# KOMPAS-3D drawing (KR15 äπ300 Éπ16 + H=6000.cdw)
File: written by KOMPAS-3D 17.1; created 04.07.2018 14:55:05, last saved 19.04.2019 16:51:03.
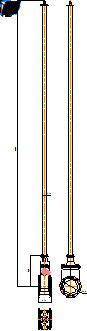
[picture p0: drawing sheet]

Sheet 1: A4, portrait

Title block, sheet 1: name: KR15 Ду300 Ру16 + / H=6000; material: Внимание! Данный продукт является объектом авторского права ООО «Торговый Дом АДЛ». / Запрещается изменение, копирование, распространение / (в том числе путем копирования на другие сайты и ресурсы в Интернете) / или любое иное использование информации и объектов без предварительного / согласия правообладателя (ООО «Торговый Дом АДЛ»).; mass: 36,7; sheets: 1; organisation: ООО "Торговый дом АДЛ"; sheet format: A4; stored path: \\adlc.lan\data\АДЛ_ПКД\3D-модели\ADL production\Клиновые задвижки серии KR ГРАНАР\Клиновые задвижки KR15 со стационарным удлинением\KOMPAS 2D\KR15 Ду300 Ру16 + H=6000.cdw

Views: Проекционный вид 6, Спереди 13, Проекционный вид 15
Referenced files in C:\Users\kka\KOMPAS_Work\Удлинения БИВАЛ ф. ADL\!Задвижки\У_ду_125-400\: Ушду125-400.a3d
Referenced files in C:\Users\kka\KOMPAS_Work\!Trash\ГРАНАР KR Задвижки с приводами и удлинениями\С приводами\: KR15 Ду300 Ру16.m3d
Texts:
  kka
  adl
  УШКЗ.100000.00.00
  Удлинение клиновой задвижки с редуктором
  Крепежное изделие ГОСТ
  Болт
  ГОСТ
  Гайка
  Лит-Масса-Масштаб
  Материал-Предприятие
  Title Specification
  Body Specification ( left align )
  Body Specificaton ( centered )
  Поз.
  Кол.
  Приме-
  чание
  Таблица спецификации
Dimensions and other numbers on the sheet: 76; 645; 270; 6000; 410; 4; 1; 58; 40Х; 019; 1:1; 36,7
